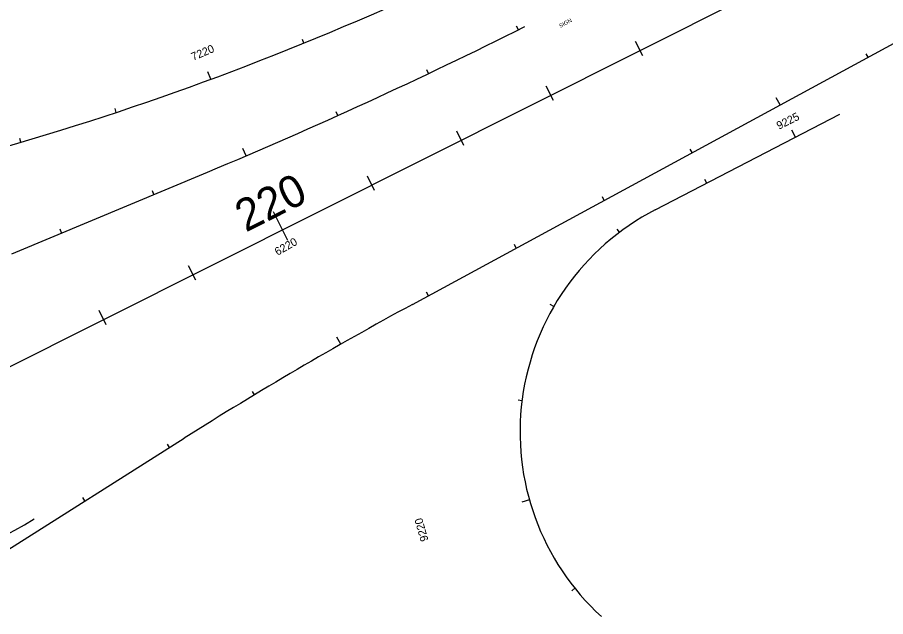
# Model space of a CAD drawing. Extents: x -5665 to 1997148, y 4 to 827579.
# Drawn here: x 1971970 to 1972838, y 802577 to 803176 of the extents above; entities that cross this region are included whole.
import ezdxf

# ---------------------------------------------------------------- set-up
doc = ezdxf.new("R2010")
doc.units = 0
for name, color, linetype in [('Default', 7, 'Continuous'), ('RD_HC_CL_Rel', 7, 'Continuous'), ('RD_HC_Data_Tic_Rel', 7, 'Continuous'), ('RD_HC_TX_Rel_Sta50', 7, 'Continuous')]:
    doc.layers.add(name, color=color, linetype=linetype)

msp = doc.modelspace()

# ---------------------------------------------------------------- linework, layer by layer
at = {"layer": 'RD_HC_CL_Rel'}
for p, q in [((1971733.64, 802712.2), (1977177.45, 805443.11)), ((1972365.14, 802889.32), (1972882.72, 803169.93)), ((1972607.83, 802983.81), (1972792.55, 803079.41)), ((1971964.79, 802939.99), (1972160.39, 803021.57)), ((1971908.89, 802611.51), (1972136.99, 802755.6))]:
    msp.add_line(p, q, dxfattribs=at)
for centre, radius, start, end in [((1971125.08, 805928.8), 3000, 284.64509, 293.84512), ((1970235.62, 807636.25), 5000, 292.64085, 296.64085), ((1972722.73, 802761.79), 250, 117.36273, 227.55396), ((1974257.34, 799399.26), 3970, 118.46505, 122.28244), ((1971799.96, 802970.88), 350, 244.77603, 302.28244)]:
    msp.add_arc(centre, radius, start, end, dxfattribs=at)
at = {"layer": 'RD_HC_Data_Tic_Rel'}
for p, q in [((1972471.13, 803163.84), (1972469.35, 803167.42)), ((1972256.77, 803150.44), (1972255.26, 803154.14)), ((1972595.44, 803137.81), (1972588.27, 803152.11)), ((1972820.67, 803136.29), (1972818.76, 803139.81)), ((1972163.55, 803114.27), (1972160.78, 803121.77)), ((1972381.25, 803120.03), (1972379.53, 803123.64)), ((1972506.06, 803092.97), (1972498.89, 803107.27)), ((1972732.76, 803088.63), (1972728.94, 803095.66)), ((1972069.17, 803081.22), (1972067.91, 803085.02)), ((1972290.5, 803078.02), (1972288.85, 803081.67)), ((1972416.68, 803048.13), (1972409.5, 803062.43)), ((1972748.15, 803056.43), (1972744.47, 803063.54)), ((1971973.74, 803051.34), (1971972.61, 803055.18)), ((1972198.93, 803037.84), (1972195.79, 803045.2)), ((1972644.84, 803040.97), (1972642.94, 803044.48)), ((1972327.29, 803003.29), (1972320.12, 803017.59)), ((1972659.33, 803010.47), (1972657.5, 803014.02)), ((1972106.7, 802999.18), (1972105.16, 803002.87)), ((1972556.93, 802993.3), (1972555.03, 802996.82)), ((1972240.6, 802953.09), (1972226.25, 802981.69)), ((1972014.41, 802960.69), (1972012.87, 802964.38)), ((1972572.32, 802961.47), (1972569.91, 802964.67)), ((1972469.02, 802945.64), (1972467.12, 802949.16)), ((1972148.53, 802913.61), (1972141.35, 802927.92)), ((1972381.11, 802897.98), (1972379.21, 802901.5)), ((1972506.43, 802887.13), (1972502.97, 802889.14)), ((1972059.14, 802868.77), (1972051.97, 802883.08)), ((1972293.61, 802849.58), (1972289.65, 802856.53)), ((1972207.33, 802799.02), (1972205.27, 802802.45)), ((1972474.69, 802793.01), (1972470.72, 802793.51)), ((1972122.33, 802746.35), (1972120.2, 802749.73)), ((1972037.79, 802692.94), (1972035.66, 802696.32)), ((1972482.11, 802693.95), (1972474.41, 802691.78)), ((1972527.52, 802605.6), (1972524.4, 802603.1))]:
    msp.add_line(p, q, dxfattribs=at)

# ---------------------------------------------------------------- texts
at = {"layer": 'Default'}
msp.add_text('SIGN', height=4, rotation=28.01393, dxfattribs=at).set_placement((1972513.08, 803165.6))
at = {"layer": 'RD_HC_TX_Rel_Sta50'}
for s, height, rotation, p in [('7220', 8, 23.12022, (1972146.03, 803132.68)), ('9225', 8, 26.64085, (1972731.59, 803063.79)), ('220', 32, 26.64085, (1972198.5, 802961.06)), ('6220', 8, 29.64612, (1972230.27, 802937.8)), ('9220', 8, 105.74425, (1972381.26, 802653.66))]:
    msp.add_text(s, height=height, rotation=rotation, dxfattribs=at).set_placement(p)

doc.saveas('drawing.dxf')
